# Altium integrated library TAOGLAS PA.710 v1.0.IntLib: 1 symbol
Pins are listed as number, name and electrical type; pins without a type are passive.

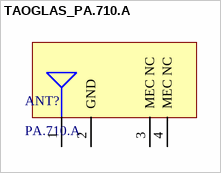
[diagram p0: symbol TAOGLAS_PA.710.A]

## TAOGLAS_PA.710.A
designator ANT?, comment PA.710.A
WARRIOR Ultra Wideband LTE/Cellular/CDMA SMD Antenna¦ 698MHz-960MHz, 1710MHz-2690MHz; ComponentLibStatus: Created; MFG: Taoglas; Temp_High: +85C; Temp_Low: -40C
footprint TAOGLAS_PA.710.A (WARRIOR Ultra Wideband LTE/Cellular/CDMA SMD Antenna)
pins: 1 RF OUT, 2 GND, 3 MEC NC, 4 MEC NC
